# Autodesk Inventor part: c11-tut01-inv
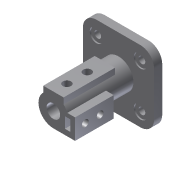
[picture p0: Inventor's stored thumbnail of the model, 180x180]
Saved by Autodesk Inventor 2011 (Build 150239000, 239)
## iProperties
Shininess: 77.0
Length Units: 11269
Angle Units: 11279
Time Units: 11290
Mass Units: 11283
Length Display Precision: 3
Angle Display Precision: 2
Created: 2001-12
Part Number: c11-tut01-inv
Document SubType Name: Modeling
Designer: Deepak Maini
Density: 1 g/cm^3
Density: 0.0
Volumn: 0.0
Area: 0.0
PropertySet Name: Model Information
Control State: 0
Master: False
Checked Out: False
Author: Deepak Maini
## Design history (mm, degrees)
node "Sketch1"
sketch "Sketch2"
  geometry: L1 (24.44, 30.488)-(-40.56, 30.488); L2 (-60.56, 10.488)-(-60.56, -54.512); L3 (-40.56, -74.512)-(24.44, -74.512); L4 (44.44, -54.512)-(44.44, 10.488); A1 r 20 centre (24.44, 10.488) between (44.44, 10.488) and (24.44, 30.488); A2 r 20 centre (-40.56, 10.488) between (-40.56, 30.488) and (-60.56, 10.488); A3 r 20 centre (-40.56, -54.512) between (-60.56, -54.512) and (-40.56, -74.512); A4 r 20 centre (24.44, -54.512) between (24.44, -74.512) and (44.44, -54.512); 2 further points
  constraints: 8 end point, 8 point on circle, 8 tangent, 4 centre point, 4 point on line, 3 equal radius, 2 parallel, 2 perpendicular, 1 horizontal
  dimensions: "d1" = 20 radius of A1; "d2" = 105 distance between parallel lines of L2 L4
extrude "Extrusion1" new body sketch "Sketch2" distance "d3" = 12; taper "d4" = 0 deg
sketch "Sketch3"
  geometry: A1 r 20 centre (-24.44, 10.488) between (-24.44, 30.488) and (-44.44, 10.488) reference; A2 r 20 centre (-24.44, -54.512) between (-44.44, -54.512) and (-24.44, -74.512) reference; A3 r 20 centre (40.56, -54.512) between (40.56, -74.512) and (60.56, -54.512) reference; A4 r 20 centre (40.56, 10.488) between (60.56, 10.488) and (40.56, 30.488) reference
hole "Hole1" sketch "Sketch3" at (-24.44, 10.488), (-24.44, -54.512), (40.56, 10.488), (40.56, -54.512) diameter "d5" = 10; stored, may be unused: countersink angle "d9" = 82 deg, drill point angle "d11" = 118 deg; dims "d6" = 6, "d7" = 20, "d8" = 2, "d10" = 8
sketch "Sketch4"
  geometry: L1 (-24.44, 30.488)-(40.56, 30.488) reference; L2 (-44.44, -54.512)-(-44.44, 10.488) reference; C1 r 22 at (8.06, -22.012)
  constraints: 1 centre point
  dimensions: "d12" = 52.5 distance from line of L2 C1.centre; "d13" = 52.5 distance from line of L1 C1.centre; "d14" = 44 diameter of C1
extrude "Extrusion2" join sketch "Sketch4" distance "d15" = 96; taper "d16" = 0 deg
sketch "Sketch5"
  geometry: L1 (-15, 16.093)-(15, 16.093); L2 (15, 16.093)-(15, 25); L3 (15, 25)-(-15, 25); L4 (-15, 25)-(-15, 16.093); 1 further point
  constraints: 8 end point, 2 parallel, 1 horizontal, 1 perpendicular, 2 other
  dimensions: "d17" = 30 distance of L2.end L3.end; "d18" = 25 distance from line of point (0, 0) L3; "d19" = 15 distance from line of point (0, 0) L4
extrude "Extrusion3" join sketch "Sketch5" distance "d20" = 76; taper "d21" = 0 deg
sketch "Sketch6"
  geometry: L1 (8, -44.012)-(40.06, -44.012); L2 (40.06, -44.012)-(40.06, -14.012); L3 (40.06, -14.012)-(8, -14.012); L4 (8, -14.012)-(8, -44.012); A1 r 22 centre (8.06, -22.012) between (-6.94, -5.918) and (23.06, -5.918) reference
  constraints: 8 end point, 2 parallel, 1 horizontal, 1 perpendicular, 1 tangent
  dimensions: "d22" = 32 distance from line of A1.centre L2; "d23" = 30 distance of L1.end L2.end
extrude "Extrusion4" join sketch "Sketch6" distance "d24" = 57; taper "d25" = 0 deg
sketch "Sketch7"
  geometry: L1 (25.06, -20.012)-(33.06, -20.012); L2 (33.06, -20.012)-(33.06, -36.012); L3 (33.06, -36.012)-(25.06, -36.012); L4 (25.06, -36.012)-(25.06, -20.012); A1 r 22 centre (8.06, -22.012) between (-6.94, -5.918) and (8, -44.012) reference
  constraints: 8 end point, 2 parallel, 1 horizontal, 1 perpendicular
  dimensions: "d26" = 8 distance of L2.end L3.end; "d27" = 16 distance of L1.end L2.end; "d28" = 25 distance from line of A1.centre L2; "d29" = 2 vertical distance of A1.centre L1.start
extrude "Extrusion5" cut sketch "Sketch7" distance "d30" = 35; taper "d31" = 0 deg
sketch "Sketch8"
  geometry: A1 r 22 centre (8.06, -22.012) between (-6.94, -5.918) and (8, -44.012) reference
hole "Hole2" sketch "Sketch8" at (8.06, -22.012) diameter "d32" = 20; stored, may be unused: countersink angle "d36" = 82 deg, drill point angle "d38" = 0 deg; dims "d33" = 6, "d34" = 20, "d35" = 2, "d37" = 96
sketch "Sketch9"
  geometry: L1 (0, 0)-(0, 76) reference; L2 (30, 0)-(0, 0) reference; 2 further points
  dimensions: "d39" = 20 distance from line of L2 point (15, 20); "d40" = 15 distance from line of L1 point (15, 20); "d41" = 30 distance of point (15, 50) point (15, 20)
hole "Hole3" sketch "Sketch9" at (15, 20), (15, 50) diameter "d42" = 12; stored, may be unused: countersink angle "d46" = 82 deg, drill point angle "d48" = 0 deg; dims "d43" = 6, "d44" = 20, "d45" = 2, "d47" = 25
sketch "Sketch10"
  geometry: L1 (30, 0)-(0, 0) reference; L2 (30, 0)-(30, 57) reference; 2 further points
  dimensions: "d49" = 15 distance from line of L1 point (15, 15); "d50" = 15 distance from line of L2 point (15, 15); "d51" = 22 distance of point (15, 37) point (15, 15)
hole "Hole4" sketch "Sketch10" at (15, 15), (15, 37) diameter "d52" = 10; stored, may be unused: countersink angle "d56" = 82 deg, drill point angle "d58" = 0 deg; dims "d53" = 6, "d54" = 20, "d55" = 2, "d57" = 7
body "Solid1"
